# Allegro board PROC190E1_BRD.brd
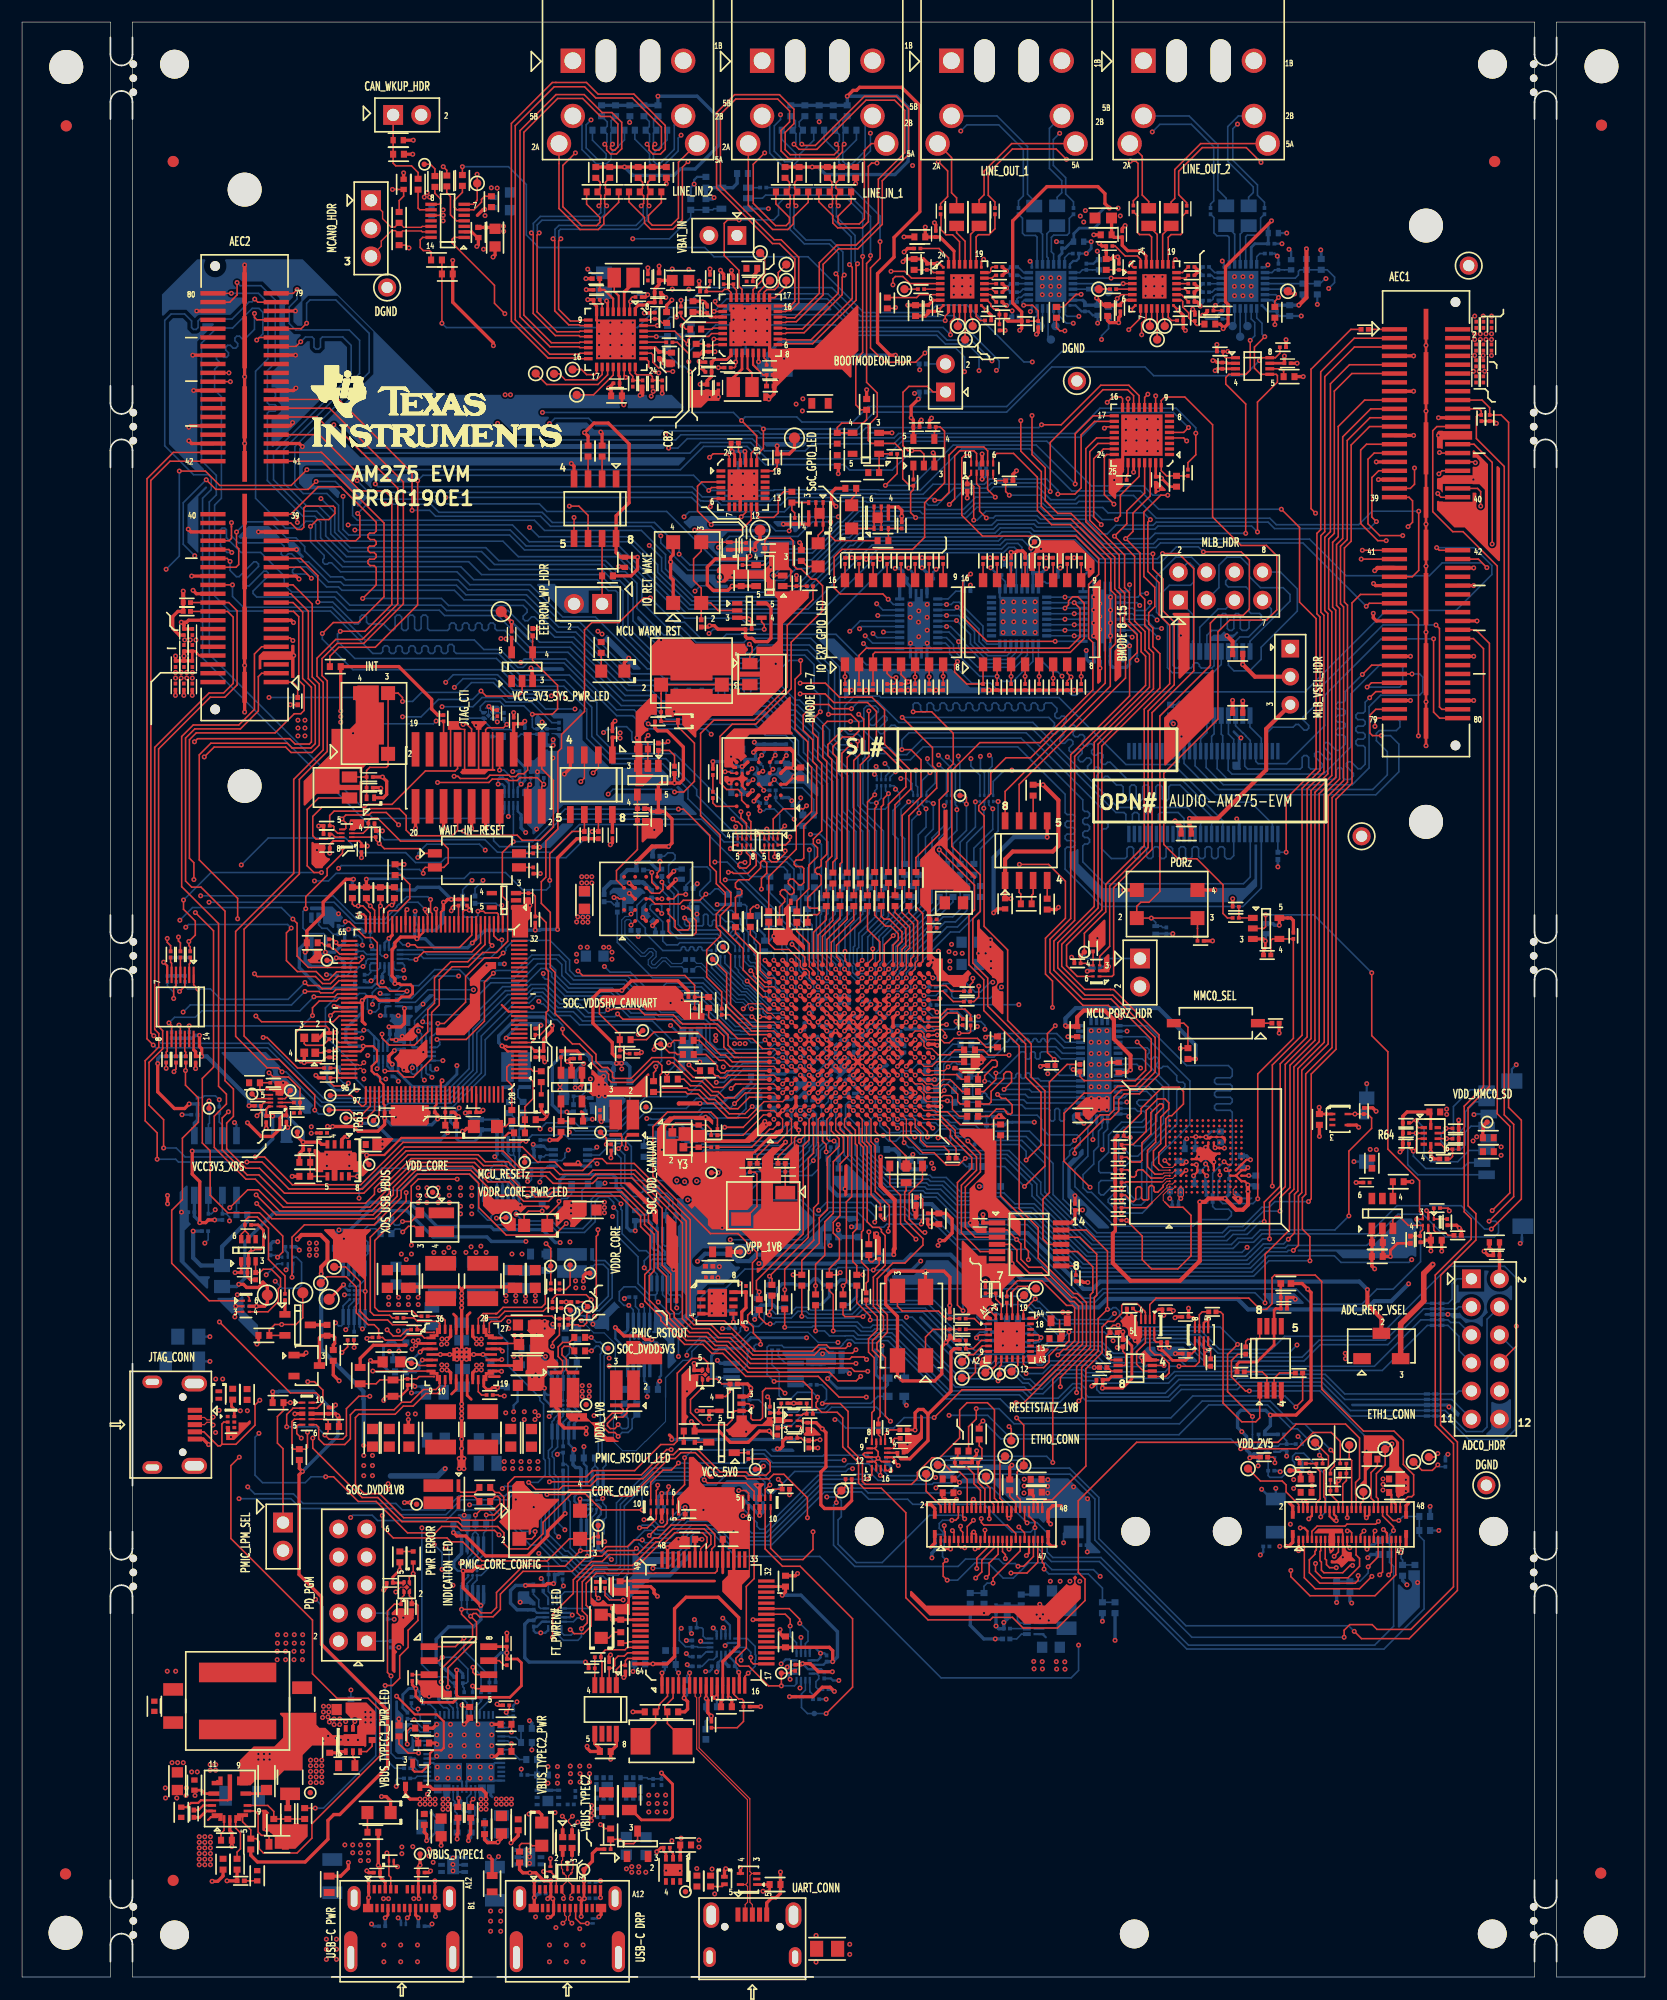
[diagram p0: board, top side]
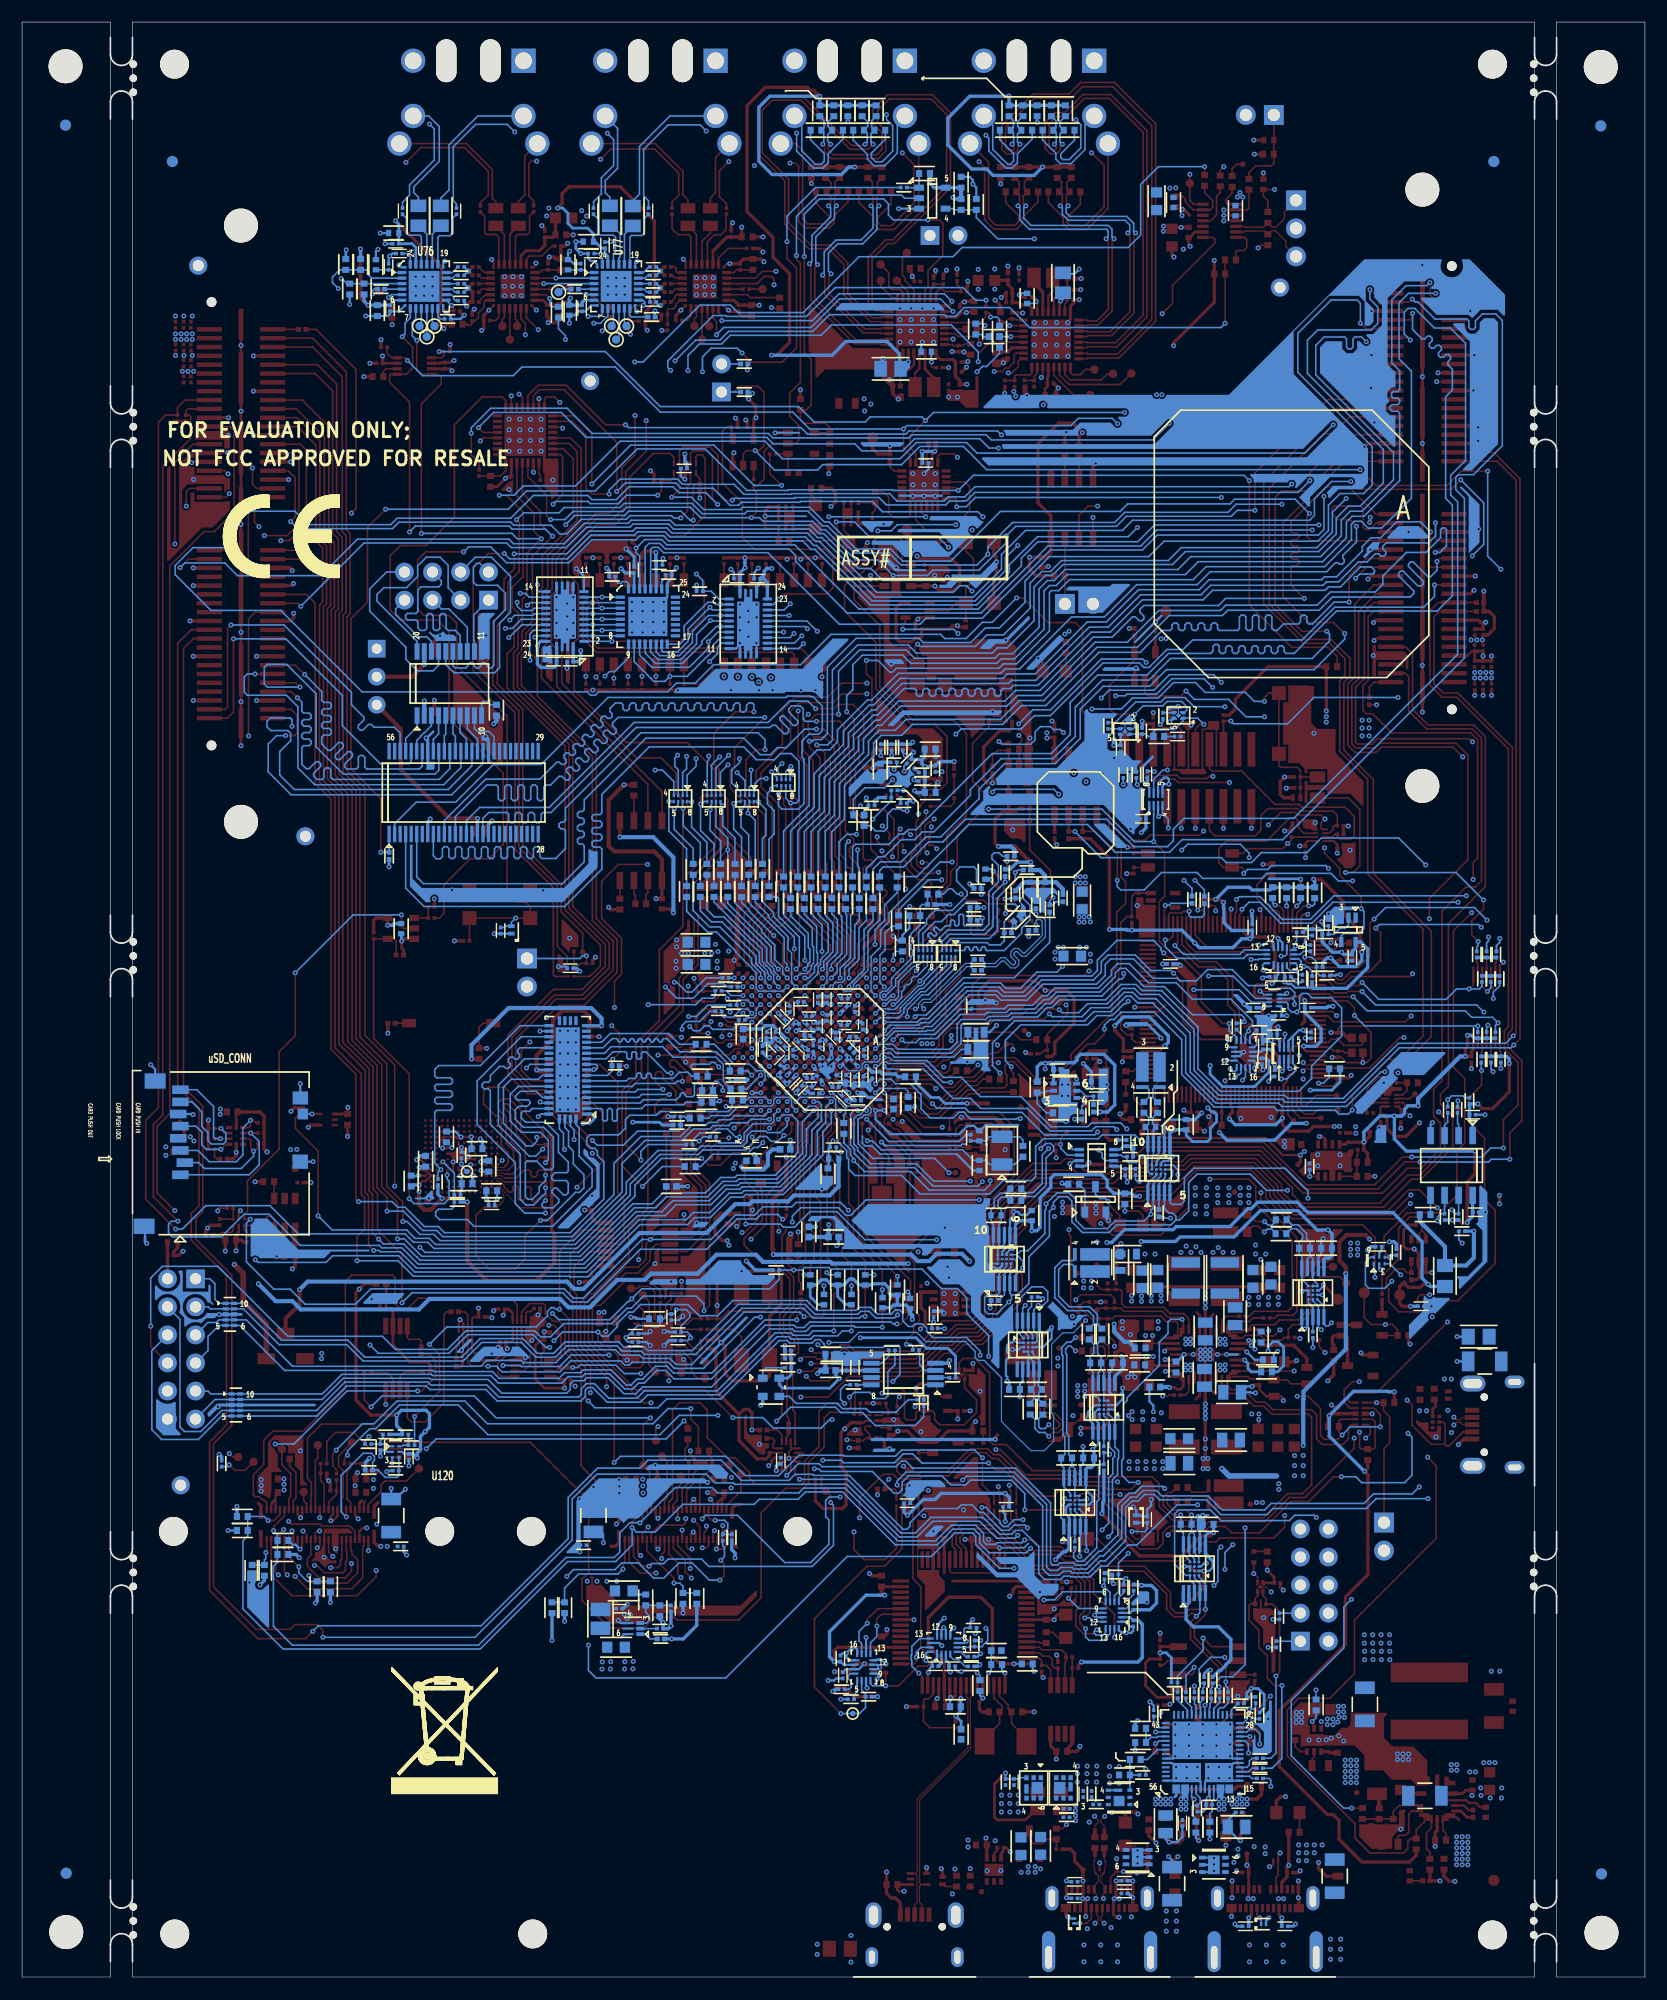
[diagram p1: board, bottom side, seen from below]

Outline 147 x 177 mm; copper layers: TOP, L02_GND1, L03_SIG1, L04_PWR1, L05_GND2, BOTTOM. Coordinates in mm from the lower left corner of the outline.
Outline path: 0,177 0,0 8,0 8,177 0,177 ; 10,177 10,0 137,0 137,177 10,177 ; 139,177 139,0 147,0 147,177 139,177

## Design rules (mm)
net group AEC1_GPIO0_1: nets AEC1_GPIO0_1 N28268314
net group AUDIO_EXT_REFCLK0: nets AUDIO_EXT_REFCLK0 N28087268
net group AUDIO_EXT_REFCLK1: nets AUDIO_EXT_REFCLK1 AUDIO_EXT_REFCLK1__R
net group AUDIO_EXT_REFCLK2: nets AUDIO_EXT_REFCLK2 AUDIO_EXT_REFCLK2_R
net group CAN_DP1: nets MCAN0_CAN_H MCAN0_CAN_L
net group CDCE_CLKOUT_1: nets CDCE_CLKOUT_1 N27176072
net group CPSW_RGMII1_TD0: nets CPSW_RGMII1_TD0 N28084397
net group CPSW_RGMII1_TD1: nets CPSW_RGMII1_TD1 N28084399
net group CPSW_RGMII1_TD2: nets CPSW_RGMII1_TD2 N28084409
net group CPSW_RGMII1_TD3: nets CPSW_RGMII1_TD3 N28084411
net group CPSW_RGMII1_TXC: nets CPSW_RGMII1_TXC CPSW_RGMII_TXC_R
net group CPSW_RGMII2_TD0: nets CPSW_RGMII2_TD0 N28084427
net group CPSW_RGMII2_TD2: nets CPSW_RGMII2_TD2 N28084431
net group CPSW_RGMII2_TD3: nets CPSW_RGMII2_TD3 N28084433
net group CPSW_RGMII2_TXC: nets CPSW_RGMII2_TXC CPSW_RGMII2_TXC_R
net group DP1_USB_SOC: nets SOC_USB0_DM SOC_USB0_DP
net group DP_CONN2: nets USBC_CONN2_DM USBC_CONN2_DP
net group DP_XDS_USB: nets XDS_USB_DM XDS_USB_DP
net group DVDD3V3: nets DVDD3V3_N DVDD3V3_P
net group HYPERBUS0_CK: nets HYPERBUS0_CK N28088261
net group HYPERBUS0_CK#: nets HYPERBUS0_CK# N28088302
net group HYPERBUS0_CS#: nets HYPERBUS0_CS# N28088339
net group HYPERBUS0_DQ0: nets HYPERBUS0_DQ0 SOC_HYPERBUS0_DQ0
net group HYPERBUS0_DQ1: nets HYPERBUS0_DQ1 SOC_HYPERBUS0_DQ1
net group HYPERBUS0_DQ2: nets HYPERBUS0_DQ2 SOC_HYPERBUS0_DQ2
net group HYPERBUS0_DQ3: nets HYPERBUS0_DQ3 SOC_HYPERBUS0_DQ3
net group HYPERBUS0_DQ4: nets HYPERBUS0_DQ4 SOC_HYPERBUS0_DQ4
net group HYPERBUS0_DQ5: nets HYPERBUS0_DQ5 SOC_HYPERBUS0_DQ5
net group HYPERBUS0_DQ6: nets HYPERBUS0_DQ6 SOC_HYPERBUS0_DQ6
net group HYPERBUS0_DQ7: nets HYPERBUS0_DQ7 SOC_HYPERBUS0_DQ7
net group HYPERBUS0_RWDS: nets HYPERBUS0_RWDS N27995683
net group MCASP0_ACLKR: nets MCASP0_ACLKR MCASP0_ACLKR_R
net group MCASP0_ACLKX: nets MCASP0_ACLKX N28061850
net group MCASP0_AFSR: nets MCASP0_AFSR MCASP0_AFSR_R
net group MCASP0_AFSX: nets MCASP0_AFSX MCASP0_AFSX_R
net group MCASP0_AXR0: nets MCASP0_AXR0 MCASP0_AXR0_R
net group MCASP0_AXR1: nets MCASP0_AXR1 MCASP0_AXR1_R
net group MCASP0_AXR2: nets MCASP0_AXR2 MCASP0_AXR2_R
net group MCASP0_AXR3: nets MCASP0_AXR3 MCASP0_AXR3_R
net group MCASP0_AXR4: nets MCASP0_AXR4 MCASP0_AXR4_R
net group MCASP0_AXR5: nets MCASP0_AXR5 MCASP0_AXR5_R
net group MCASP0_AXR6_R: nets MCASP0_AXR6_R UART2_RXD_FET
net group MCASP0_AXR7: nets MCASP0_AXR7 MCASP0_AXR7_R
net group MCASP0_AXR8_R: nets MCASP0_AXR8_R OBSCLK0
net group MCASP0_AXR9: nets MCASP0_AXR9 MCASP0_AXR9_R
net group MCASP1_ACLKR_R: nets MCASP1_ACLKR_R PCM6240_MCASP1_ACLKR
net group MCASP1_ACLKX_R: nets MCASP1_ACLKX_R TAD5212_MCASP1_ACLKX
net group MCASP1_AFSR_R: nets MCASP1_AFSR_R PCM6240_MCASP1_AFSR
net group MCASP1_AFSX_R: nets MCASP1_AFSX_R TAD5212_MCASP1_AFSX
net group MCASP1_AXR0_R: nets MCASP1_AXR0_R PCM6240_MCASP1_AXR0
net group MCASP1_AXR2_R: nets MCASP1_AXR2_R PCM6240_MCASP1_AXR2
net group MCASP2_ACLKR: nets MCASP2_ACLKR MCASP2_ACLKR_R
net group MCASP2_ACLKX: nets MCASP2_ACLKX MCASP2_ACLKX_R
net group MCASP2_AFSR: nets MCASP2_AFSR MCASP2_AFSR_R
net group MCASP2_AFSX: nets MCASP2_AFSX MCASP2_AFSX_R
net group MCASP2_AXR0: nets MCASP2_AXR0 MCASP2_AXR0_R
net group MCASP2_AXR1: nets MCASP2_AXR1 MCASP2_AXR1_R
net group MCASP2_AXR2: nets MCASP2_AXR2 MCASP2_AXR2_R
net group MCASP2_AXR3: nets MCASP2_AXR3 MCASP2_AXR3_R
net group MCASP2_AXR4: nets MCASP2_AXR4 MCASP2_AXR4_R
net group MCASP2_AXR5: nets MCASP2_AXR5 MCASP2_AXR5_R
net group MCASP3_ACLKX: nets MCASP3_ACLKX N28066500
net group MCASP3_AFSX: nets MCASP3_AFSX N28066472
net group MCASP3_AXR0: nets MCASP3_AXR0 N28066355
net group MCASP3_AXR1: nets MCASP3_AXR1 N28066391
net group MCASP3_AXR2: nets MCASP3_AXR2 N28066418
net group MCASP3_AXR3: nets MCASP3_AXR3 N28066445
net group MCASP4_ACLKR_R: nets MCASP4_ACLKR_FET MCASP4_ACLKR_R
net group MCASP4_AFSR_R: nets MCASP4_AFSR_FET MCASP4_AFSR_R
net group MCASP4_AXR0_R: nets MCASP4_AXR0_FET MCASP4_AXR0_R
net group MCASP4_AXR3_R: nets MCASP4_AXR3_FET MCASP4_AXR3_R
net group MCASP4_AXR4_R: nets MCASP4_AXR4_FET MCASP4_AXR4_R
net group MCASP4_AXR5_R: nets MCASP4_AXR5_FET MCASP4_AXR5_R
net group OSC1_XI: nets N27975321 OSC1_XI
net group OSC1_XO: nets N27975317 OSC1_XO
net group OSPI_CLK: nets OSPI_CLK SOC_OSPI_CLK
net group OSPI_DQS: nets OSPI_DQS OSPI_DQS_SOC
net group PCMPCM1_IN1: nets PCM1_IN1N PCM1_IN1P
net group PCMPCM1_IN2: nets PCM1_IN2N PCM1_IN2P
net group PCMPCM1_IN3: nets PCM1_IN3N PCM1_IN3P
net group PCMPCM1_IN4: nets PCM1_IN4N PCM1_IN4P
net group PCMPCM2_IN1: nets PCM2_IN1N PCM2_IN1P
net group PCMPCM2_IN2: nets PCM2_IN2N PCM2_IN2P
net group PCMPCM2_IN3: nets PCM2_IN3N PCM2_IN3P
net group PCMPCM2_IN4: nets PCM2_IN4N PCM2_IN4P
net group RESET_STATZ: nets RESET_STATZ RESETSTATZ_1V8
net group SEC_REF_N: nets N27175817 SEC_REF_N
net group SEC_REF_P: nets N27175821 SEC_REF_P
net group SOC_DVDD1V8: nets SOC_DVDD1V8_N SOC_DVDD1V8_P
net group SOC_DVDD3V3: nets SOC_DVDD3V3_N SOC_DVDD3V3_P
net group SOC_MMC0_CLK: nets MMC0_CLK SOC_MMC0_CLK
net group SOC_MMC0_CMD_R: nets SOC_MMC0_CMD SOC_MMC0_CMD_R
net group SOC_MMC0_DAT0_R: nets SOC_MMC0_DAT0 SOC_MMC0_DAT0_R
net group SOC_MMC0_DAT1_R: nets SOC_MMC0_DAT1 SOC_MMC0_DAT1_R
net group SOC_MMC0_DAT2_R: nets SOC_MMC0_DAT2 SOC_MMC0_DAT2_R
net group SOC_MMC0_DAT3_R: nets SOC_MMC0_DAT3 SOC_MMC0_DAT3_R
net group SOC_MMC0_DAT4_R: nets SOC_MMC0_DAT4 SOC_MMC0_DAT4_R
net group SOC_MMC0_DAT5_R: nets SOC_MMC0_DAT5 SOC_MMC0_DAT5_R
net group SOC_MMC0_DAT6_R: nets SOC_MMC0_DAT6 SOC_MMC0_DAT6_R
net group SOC_MMC0_DAT7_R: nets SOC_MMC0_DAT7 SOC_MMC0_DAT7_R
net group SOC_OSPI_DQ0: nets OSPI_DQ0 SOC_OSPI_DQ0
net group SOC_OSPI_DQ1: nets OSPI_DQ1 SOC_OSPI_DQ1
net group SOC_OSPI_DQ2: nets OSPI_DQ2 SOC_OSPI_DQ2
net group SOC_OSPI_DQ3: nets OSPI_DQ3 SOC_OSPI_DQ3
net group SOC_OSPI_DQ4: nets OSPI_DQ4 SOC_OSPI_DQ4
net group SOC_OSPI_DQ5: nets OSPI_DQ5 SOC_OSPI_DQ5
net group SOC_OSPI_DQ6: nets OSPI_DQ6 SOC_OSPI_DQ6
net group SOC_OSPI_DQ7: nets OSPI_DQ7 SOC_OSPI_DQ7
net group SOC_VDD_CANUART: nets SOC_VDD_CANUART_N SOC_VDD_CANUART_P
net group SOC_VDDSHV_CANUART: nets SOC_VDDSHV_CANUART_N SOC_VDDSHV_CANUART_P
net group VDD_0V85: nets VDD_0V85_N VDD_0V85_P
net group VDD_1V8: nets VDD_1V8_N VDD_1V8_P
net group VDD_CANUART: nets VDD_CANUART_N VDD_CANUART_P
net group VDD_CORE: nets VDD_CORE_N VDD_CORE_P
net group VDDA_1V8: nets VDDA_1V8_N VDDA_1V8_P
net group VDDR_CORE: nets VDDR_CORE_N VDDR_CORE_P
net group VDDSHV_CANUART: nets VDDSHV_CANUART_N VDDSHV_CANUART_P
net group WKUP_LFOSCO_XO: nets N27972730 WKUP_LFOSCO_XO
net group CPSW_RGMII2_TD1: nets N28084429
net group EMMC_MG: nets EMMC_CLK EMMC_CMD EMMC_D0 EMMC_D1 EMMC_D2 EMMC_D3 EMMC_D4 EMMC_D5 EMMC_D6 EMMC_D7
net group MCASP1_AXR1_R: nets MCASP1_AXR1_R TAD5212_1_DIN TAD5212_2_DIN TAD5212_3_DIN TAD5212_4_DIN TAD5212_MCASP1_AXR1
net group MCASP3_ACLKR: nets MCASP3_ACLKR MCASP4_ACLKX_FET MCASP4_ACLKX_R
net group MCASP3_AFSR: nets MCASP3_AFSR MCASP4_AFSX_FET MCASP4_AFSX_R
net group OSPI0_CSN0: nets N29295413 N29295438 OSPI0_CSN0 OSPI_CS
net group PWR: nets N24307354 N24307356 VCC1V8_SYS_N VCC_CORE_N VDDA_1V8_FB3 VDDA_ADC0
net group RGMII1_RD: nets CPSW_RGMII1_RD0 CPSW_RGMII1_RD1 CPSW_RGMII1_RD2 CPSW_RGMII1_RD3 CPSW_RGMII1_RX_DV CPSW_RGMII1_RXC
net group RGMII2_RD: nets CPSW_RGMII2_RD0 CPSW_RGMII2_RD1 CPSW_RGMII2_RD2 CPSW_RGMII2_RD3 CPSW_RGMII2_RX_DV CPSW_RGMII2_RXC
net group RGMII2_TD: nets CPSW_RGMII2_TX_EN
net group RGMII_TD: nets CPSW_RGMII1_TX_EN

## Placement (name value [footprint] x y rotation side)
C1  0.022uF  [CAP0402_0-75]  34.07 166.31 0 top
C2  0.1uF  [CAP0402_0-75]  58.36 163.39 270 top
C3  0.1uF  [CAP0402_0-75]  75.51 163.39 270 top
C11  22uF  [CAP0402_1]  51.63 161.63 0 top
C12  22uF  [CAP0402_1]  53.55 161.63 180 top
C13  22uF  [CAP0402_1]  55.47 161.63 0 top
C14  22uF  [CAP0402_1]  57.42 161.63 180 top
C15  22uF  [CAP0402_1]  68.77 161.63 0 top
C16  22uF  [CAP0402_1]  70.72 161.63 180 top
C17  22uF  [CAP0402_1]  72.66 161.63 0 top
C18  22uF  [CAP0402_1]  74.61 161.63 180 top
C20  1uF  [CAP0201_0-5]  100.66 160.11 270 top
C21  1uF  [CAP0201_0-5]  105.49 160.1 270 top
C22  1uF  [CAP0201_0-5]  83.2 159.88 270 top
C23  1uF  [CAP0201_0-5]  88.13 159.88 270 top
C24  47uF  [CAP0805_1-5]  84.65 159.34 270 top
C25  47uF  [CAP0805_1-5]  86.68 159.34 270 top
C26  47uF  [CAP0805_1-5]  102.05 159.34 270 top
C27  47uF  [CAP0805_1-5]  104.08 159.34 270 top
C28  0.1uF  [CAP0402_0-75]  122.76 65.24 0 top
C29  0.1uF  [CAP0201_0-5]  82.76 157.82 90 top
C30  0.1uF  [CAP0201_0-5]  99.65 157.79 90 top
C31  10uF  [CAP0402_0-75]  98.2 157.74 180 top
C32  10uF  [CAP0402_0-75]  81.32 157.55 180 top
C33  4.7uF  [CAP0402_0-75]  122.77 66.5 180 top
C35  1uF  [CAP0201_0-5]  98.48 156.72 180 top
C37  0.1uF  [CAP0402_0-75]  128.1 66.71 0 top
C38  1uF  [CAP0201_0-5]  81.09 156.5 180 top
C42  10uF  [CAP0402_0-75]  80.8 155.06 90 top
C43  10uF  [CAP0402_0-75]  98.2 155.06 90 top
C45  0.1uF  [CAP0201_0-5]  81.95 154.85 90 top
C46  0.1uF  [CAP0201_0-5]  99.35 154.85 90 top
C47  0.1uF  [CAP0201_0-5]  88.52 154.83 0 top
C48  0.1uF  [CAP0201_0-5]  105.92 154.83 0 top
C49  0.1uF  [CAP0402_0-75]  66.1 154.7 0 top
C50  0.1uF  [CAP0201_0-5]  88.52 154.07 0 top
C51  0.1uF  [CAP0201_0-5]  105.92 154.07 0 top
C52  2.2uF  [CAP0201_0-75]  57.7 153.95 90 top
C53  0.1uF  [CAP0201_0-5]  56.69 153.89 270 top
C54  2.2uF  [CAP0201_0-75]  51.98 153.77 180 top
C55  1uF  [CAP0201_0-5]  65.91 153.52 0 top
C56  0.1uF  [CAP0201_0-5]  88.52 153.31 0 top
C57  0.1uF  [CAP0201_0-5]  105.92 153.31 0 top
C60  0.1uF  [CAP0201_0-5]  52.04 152.76 0 top
C61  0.1uF  [CAP0201_0-5]  88.52 152.55 0 top
C62  0.1uF  [CAP0201_0-5]  105.92 152.55 0 top
C63  1uF  [CAP0201_0-5]  57.58 152.5 0 top
C64  0.1uF  [CAP0201_0-5]  55.85 152.11 0 top
C65  1uF  [CAP0201_0-5]  52.04 151.87 180 top
C66  1uF  [CAP0201_0-5]  88.52 151.66 0 top
C67  1uF  [CAP0201_0-5]  105.92 151.66 0 top
C68  0.1uF  [CAP0201_0-5]  57.58 151.61 0 top
C69  1uF  [CAP0201_0-5]  121.78 71.93 180 top
C70  220pF  [CAP0402_0-75]  124.66 72 0 top
C71  10uF  [CAP0402_0-75]  60.77 151.24 90 top
C72  0.1uF  [CAP0201_0-5]  82.08 151.09 270 top
C73  0.1uF  [CAP0201_0-5]  99.48 151.09 270 top
C74  0.1uF  [CAP0201_0-5]  62.07 150.95 90 top
C75  10uF  [CAP0402_0-75]  80.93 150.88 270 top
C76  10uF  [CAP0402_0-75]  98.33 150.88 270 top
C77  10uF  [CAP0402_0-75]  58.38 150.25 90 top
C78  0.1uF  [CAP0201_0-5]  57.33 150.42 90 top
C81  0.1uF  [CAP0201_0-5]  62.18 147.44 270 top
C82  10uF  [CAP0402_0-75]  61.06 147.38 270 top
C84  0.1uF  [CAP0201_0-5]  57.69 146.86 270 top
C85  10uF  [CAP0402_0-75]  58.83 146.58 270 top
C86  0.1uF  [CAP0201_0-5]  62.18 146.21 180 top
C87  1uF  [CAP0201_0-5]  67.71 145.95 0 top
C88  2.2uF  [CAP0402_0-75]  132.82 74.73 180 top
C89  0.1uF  [CAP0201_0-5]  63.91 145.71 180 top
C90  1uF  [CAP0201_0-5]  62.18 145.32 180 top
C92  0.1uF  [CAP0201_0-5]  67.71 145.06 180 top
C93  0.1uF  [CAP0402_0-75]  132.81 75.99 180 top
C95  1uF  [CAP0201_0-5]  53.85 144.3 180 top
C96  2.2uF  [CAP0201_0-75]  67.77 144.05 0 top
C97  0.1uF  [CAP0201_0-5]  63.07 143.93 90 top
C98  2.2uF  [CAP0201_0-75]  62.05 143.87 270 top
C99  0.1uF  [CAP0201_0-5]  114.63 146.11 0 top
C100  0.1uF  [CAP0402_0-75]  53.85 143.16 180 top
C101  0.1uF  [CAP0201_0-5]  108.71 145.89 90 top
C102  0.1uF  [CAP0402_0-75]  117.51 77.64 90 top
C103  0.1uF  [CAP0402_0-75]  127.96 78.32 180 top
C104  12pF  [CAP0201_0-5]  84.03 58.36 90 top
C105  12pF  [CAP0201_0-5]  84.04 59.89 90 top
C107  4700pF  [CAP0402_0-75]  34.56 162.31 90 top
C109  0.1uF  [CAP0402_0-75]  73.84 137.3 270 top
C121  10uF  [CAP0402_0-75]  93.55 57.8 0 top
C122  0.01uF  [CAP0201_0-5]  65.16 137.08 0 bottom
C126  0.01uF  [CAP0201_0-5]  102.68 135.56 90 top
C128  0.1uF  [CAP0201_0-5]  131.71 149.59 90 top
C129  0.1uF  [CAP0201_0-5]  132.37 149.59 90 top
C130  1uF  [CAP0201_0-5]  133.11 149.59 90 top
C133  0.1uF  [CAP0201_0-5]  131.7 147.53 270 top
C134  1uF  [CAP0201_0-5]  132.36 147.53 270 top
C135  1uF  [CAP0201_0-5]  133.1 147.53 270 top
C136  0.1uF  [CAP0201_0-5]  81.02 140.33 0 top
C137  0.1uF  [CAP0201_0-5]  131.7 146.1 90 top
C138  1uF  [CAP0201_0-5]  132.36 146.1 90 top
C140  0.1uF  [CAP0201_0-5]  53.47 112.51 90 top
C141  0.1uF  [CAP0201_0-5]  131.7 144.65 270 top
C142  1uF  [CAP0201_0-5]  132.36 144.65 270 top
C146  0.1uF  [CAP0402_0-75]  112.66 94.92 270 bottom
C147  0.1uF  [CAP0201_0-5]  53.47 103.38 270 top
C148  0.1uF  [CAP0402_0-75]  65.14 126.42 90 top
C149  4.7uF  [CAP0402_0-75]  70.53 109.02 90 top
C150  0.1uF  [CAP0201_0-5]  103.57 60.45 180 top
C151  0.1uF  [CAP0201_0-5]  103.45 57.48 180 top
C160  1uF  [CAP0201_0-5]  14.66 121.77 90 top
C161  0.1uF  [CAP0201_0-5]  15.42 121.77 90 top
C164  0.1uF  [CAP0201_0-5]  86.77 68.28 180 top
C165  0.1uF  [CAP0201_0-5]  95.37 69.72 270 top
C167  1uF  [CAP0201_0-5]  14.66 120.32 270 top
C168  0.1uF  [CAP0201_0-5]  15.42 120.32 270 top
C169  0.1uF  [CAP0201_0-5]  44.53 113.75 90 top
C170  1uF  [CAP0201_0-5]  13.9 118.89 90 top
C171  1uF  [CAP0201_0-5]  14.66 118.89 90 top
C172  0.1uF  [CAP0201_0-5]  15.42 118.89 90 top
C174  1uF  [CAP0201_0-5]  13.89 116.83 270 top
C175  0.1uF  [CAP0201_0-5]  14.65 116.83 270 top
C176  0.1uF  [CAP0201_0-5]  15.42 116.83 270 top
C182  100pF  [CAP0201_0-5]  77.64 65.29 270 top
C188  100pF  [CAP0201_0-5]  87.65 77.9 180 bottom
C190  0.01uF  [CAP0201_0-5]  45.87 97.85 270 top
C192  0.1uF  [CAP0201_0-5]  15.72 83.08 270 top
C197  1uF  [CAP0201_0-5]  50.27 83.16 180 top
C201  10uF  [CAP0402_1]  45.76 55.42 0 bottom
C202  10uF  [CAP0402_1]  83.04 68.65 270 top
C203  0.1uF  [CAP0201_0-5]  27.8 93.68 270 top
C205  18pF  [CAP0402_0-75]  61.28 76.68 90 top
C207  1uF  [CAP0201_0-5]  52.34 78.21 270 top
C208  0.01uF  [CAP0201_0-5]  42.99 91.72 180 bottom
C209  18pF  [CAP0402_0-75]  61.28 74.67 90 top
C213  12pF  [CAP0402_0-75]  60.29 76.16 270 bottom
C215  0.1uF  [CAP0201_0-5]  46.48 85.59 270 top
C216  12pF  [CAP0402_0-75]  60.29 73.48 90 bottom
C217  12pF  [CAP0201_0-5]  27.81 85.2 270 top
C221  0.01uF  [CAP0201_0-5]  46.48 83.56 270 top
C222  1uF  [CAP0201_0-5]  47.24 83.56 270 top
C223  12pF  [CAP0201_0-5]  27.81 83.54 90 top
C224  1uF  [CAP0201_0-5]  71.57 81.23 270 bottom
C225  0.1uF  [CAP0201_0-5]  27.65 81.41 0 top
C226  22uF  [CAP0603_1]  33.08 63.2 270 top
C227  47uF  [CAP0805_1-5]  34.99 63.2 270 top
C228  47uF  [CAP0805_1-5]  44.65 63.2 270 top
C229  22uF  [CAP0603_1]  46.48 63.2 270 top
C231  0.1uF  [CAP0201_0-5]  33.12 78.29 180 top
C232  0.01uF  [CAP0201_0-5]  37.11 78.29 180 top
C233  1uF  [CAP0201_0-5]  38.61 78.29 0 top
C234  0.01uF  [CAP0201_0-5]  40.85 78.29 180 top
C235  0.1uF  [CAP0201_0-5]  22.12 77.67 90 top
C236  0.1uF  [CAP0201_0-5]  23.94 77.72 90 top
C240  2.2uF  [CAP0402_0-75]  38.82 77.12 0 top
C241  1uF  [CAP0201_0-5]  27.34 76.42 180 top
C242  2.2uF  [CAP0603_1]  45.72 59.03 0 top
C243  15pF  [CAP0201_0-5]  25.74 74.9 0 top
C244  2.2uF  [CAP0402_0-75]  31.62 75.38 0 top
C245  100pF  [CAP0201_0-5]  60.92 87.42 270 top
C246  2.2uF  [CAP0603_1]  45.72 55.37 0 top
C247  2.2uF  [CAP0201_0-75]  62.24 64.34 180 top
C248  100pF  [CAP0201_0-5]  55.31 83.6 0 top
C249  2.2uF  [CAP0603_1]  33.46 55.69 180 top
C250  4.7uF  [CAP0402_0-75]  19.08 52.76 90 top
C251  0.1uF  [CAP0201_0-5]  62.22 63.35 180 top
C254  2.2uF  [CAP0603_1]  45.72 53.57 0 top
C255  1uF  [CAP0201_0-5]  65.57 62.28 90 top
C256  2.2uF  [CAP0603_1]  33.26 48.82 90 top
C257  22uF  [CAP0603_1]  35.04 48.82 90 top
C258  22uF  [CAP0603_1]  44.27 48.82 90 top
C259  2.2uF  [CAP0603_1]  42.18 48.74 180 bottom
C260  0.1uF  [CAP0603_1]  46.14 48.81 90 top
C261  0.1uF  [CAP0603_1]  31.75 48.82 90 top
C262  0.1uF  [CAP0402_0-75]  52.83 20.42 0 top
C263  4.7uF  [CAP0402_0-75]  54.17 35.34 270 top
C264  0.1uF  [CAP0402_0-75]  54.23 32.84 270 top
C265  1uF  [CAP0201_0-5]  77.63 56.74 0 bottom
C266  0.1uF  [CAP0201_0-5]  77.63 55.98 180 bottom
C267  0.1uF  [CAP0402_0-75]  20.39 52.74 90 top
C269  18pF  [CAP0402_0-75]  56.89 24 180 top
C270  18pF  [CAP0402_0-75]  58.94 24 0 top
C271  10uF  [CAP0402_0-75]  124.31 45.09 0 top
C272  10uF  [CAP0402_0-75]  83.88 45.09 0 top
C273  10uF  [CAP0402_0-75]  116.31 45.09 0 top
C274  10uF  [CAP0402_0-75]  91.86 45.06 0 top
C275  0.1uF  [CAP0402_0-75]  60.48 39.63 0 top
C276  0.1uF  [CAP0402_0-75]  116.31 43.88 0 top
C277  0.1uF  [CAP0402_0-75]  124.32 43.87 0 top
C278  0.1uF  [CAP0402_0-75]  83.88 43.84 0 top
C279  0.1uF  [CAP0402_0-75]  91.88 43.9 0 top
C280  0.1uF  [CAP0402_0-75]  63.8 24.47 180 top
C281  0.1uF  [CAP0402_0-75]  63.96 39.63 180 top
C282  0.1uF  [CAP0201_0-5]  65.63 24.48 180 top
C283  0.01uF  [CAP0201_0-5]  58.4 11.71 0 top
C284  0.1uF  [CAP0201_0-5]  71.57 55.2 270 bottom
C285  2.2uF  [CAP0402_0-75]  60.11 11.95 0 top
C286  1uF  [CAP0201_0-5]  72.33 55.2 270 bottom
C287  10uF  [CAP0402_0-75]  61.12 8.69 270 top
C288  0.1uF  [CAP0402_0-75]  69.15 30.34 270 top
C289  0.1uF  [CAP0402_0-75]  69.15 35.84 270 top
C290  10uF  [CAP0402_0-75]  73.74 56.38 180 bottom
C291  0.1uF  [CAP0402_0-75]  62.37 8.69 270 top
C292  0.1uF  [CAP0201_0-5]  43.91 30.19 90 top
C293  0.1uF  [CAP0201_0-5]  71.12 49.91 270 top
C295  0.1uF  [CAP0402_0-75]  68.21 8.37 0 top
C300  0.01uF  [CAP0201_0-5]  33.3 35.68 0 top
C301  0.01uF  [CAP0201_0-5]  43.85 24.6 180 top
C302  10uF  [CAP0603_1]  29.29 24.21 0 top
C303  4.7uF  [CAP0402_0-75]  40.54 23.95 270 top
C305  220pF  [CAP0402_0-75]  43.84 22.88 180 top
C306  220pF  [CAP0402_0-75]  36.1 22.53 0 top
C307  220pF  [CAP0402_0-75]  34.14 22.28 90 top
C308  330pF  [CAP0402_0-75]  31.71 21.94 90 top
C309  4.7uF  [CAP0402_0-75]  36.37 21.18 0 top
C310  1uF  [CAP0402_0-75]  27.86 20.79 90 top
C312  220pF  [CAP0402_0-75]  43.84 20.42 180 top
C317  47uF  [CAP0805_1-5]  52.93 15.92 270 top
C318  47uF  [CAP0805_1-5]  55.01 15.91 270 top
C319  10uF  [CAP0402_0-75]  39.48 14.9 90 top
C320  10uF  [CAP0402_0-75]  40.63 14.9 90 top
C321  0.1uF  [CAP0402_0-75]  36.43 14.26 270 top
C322  10uF  [CAP0603_1]  43.42 13.78 270 top
C323  0.1uF  [CAP0402_0-75]  44.94 13.78 270 top
C324  10uF  [CAP0603_1]  37.96 13.54 270 top
C325  0.1uF  [CAP0402_0-75]  41.89 13.43 270 top
C326  0.01uF  [CAP0201_0-5]  36.17 9.46 0 top
C327  0.01uF  [CAP0201_0-5]  32.14 9.45 180 top
C329  0.1uF  [CAP0402_0-75]  72.2 168.97 270 bottom
C330  0.1uF  [CAP0402_0-75]  55.06 168.97 270 bottom
C331  22uF  [CAP0402_1]  75.09 167.21 180 bottom
C332  22uF  [CAP0402_1]  73.14 167.21 0 bottom
C333  22uF  [CAP0402_1]  71.22 167.21 180 bottom
C334  22uF  [CAP0402_1]  69.3 167.21 0 bottom
C335  22uF  [CAP0402_1]  57.94 167.21 180 bottom
C336  22uF  [CAP0402_1]  56 167.21 0 bottom
C337  22uF  [CAP0402_1]  54.08 167.21 180 bottom
C338  22uF  [CAP0402_1]  52.16 167.21 0 bottom
C340  0.1uF  [CAP0402_0-75]  61.94 162.5 90 bottom
C341  1uF  [CAP0201_0-5]  112.54 159.88 270 bottom
C342  1uF  [CAP0201_0-5]  107.65 159.88 270 bottom
C343  1uF  [CAP0201_0-5]  95.24 159.88 270 bottom
C344  1uF  [CAP0201_0-5]  90.26 159.88 270 bottom
C345  47uF  [CAP0805_1-5#2]  111.1 159.47 270 bottom
C346  47uF  [CAP0805_1-5#2]  109.07 159.47 270 bottom
C347  47uF  [CAP0805_1-5#2]  93.76 159.47 270 bottom
C348  47uF  [CAP0805_1-5#2]  91.68 159.44 270 bottom
C349  10uF  [CAP0402_0-75]  113.34 157.9 0 bottom
C350  10uF  [CAP0402_0-75]  95.7 157.12 0 bottom
C351  0.1uF  [CAP0201_0-5]  113.16 156.93 0 bottom
C352  0.1uF  [CAP0201_0-5]  94.2 156.8 90 bottom
C353  1uF  [CAP0201_0-5]  112.85 156.04 0 bottom
C354  1uF  [CAP0201_0-5]  95.45 156.04 0 bottom
C355  10uF  [CAP0402_0-75]  114.95 155.03 90 bottom
C356  10uF  [CAP0402_0-75]  97.55 155.03 90 bottom
C357  0.1uF  [CAP0201_0-5]  113.8 154.85 90 bottom
C358  0.1uF  [CAP0201_0-5]  96.4 154.85 90 bottom
C359  0.1uF  [CAP0201_0-5]  107.24 154.83 180 bottom
C360  0.1uF  [CAP0201_0-5]  89.84 154.83 180 bottom
C361  0.1uF  [CAP0201_0-5]  107.24 154.07 180 bottom
C362  0.1uF  [CAP0201_0-5]  89.84 154.07 180 bottom
C363  1uF  [CAP0805_1-5#2]  52.71 153.4 90 bottom
C364  0.1uF  [CAP0201_0-5]  107.24 153.31 180 bottom
C365  0.1uF  [CAP0201_0-5]  89.84 153.31 180 bottom
C366  0.1uF  [CAP0201_0-5]  107.24 152.55 180 bottom
C367  0.1uF  [CAP0201_0-5]  89.84 152.55 180 bottom
C368  10uF  [CAP0402_0-75]  55.96 151.99 90 bottom
C369  1uF  [CAP0201_0-5]  107.24 151.78 180 bottom
C370  1uF  [CAP0201_0-5]  89.84 151.66 180 bottom
C371  0.1uF  [CAP0201_0-5]  113.67 151.09 270 bottom
C372  0.1uF  [CAP0201_0-5]  96.27 151.09 270 bottom
C373  10uF  [CAP0402_0-75]  114.82 150.88 270 bottom
C374  10uF  [CAP0402_0-75]  97.43 150.91 270 bottom
C378  10uF  [CAP0402_0-75]  65.09 147.15 0 bottom
C379  1uF  [CAP0805_1-5#2]  68.33 145.61 0 bottom
C382  0.1uF  [CAP0201_0-5]  87.58 58.39 0 bottom
C383  0.1uF  [CAP0201_0-5]  87.58 57.63 0 bottom
C384  0.1uF  [CAP0201_0-5]  88.21 59.75 270 bottom
C385  10uF  [CAP0402_0-75]  89.72 59.59 0 bottom
C386  0.1uF  [CAP0201_0-5]  91.46 58.25 180 bottom
C387  0.1uF  [CAP0201_0-5]  91.46 57.49 180 bottom
C388  0.1uF  [CAP0402_0-75]  64.75 111.17 180 bottom
C389  0.1uF  [CAP0402_0-75]  69.26 109.36 270 bottom
C390  0.1uF  [CAP0402_0-75]  64.74 107.24 180 bottom
C391  0.1uF  [CAP0201_0-5]  89.28 127.84 0 bottom
C393  0.1uF  [CAP0201_0-5]  91.56 127.41 270 bottom
C394  0.1uF  [CAP0201_0-5]  82.25 126.61 180 bottom
C395  0.1uF  [CAP0201_0-5]  80.41 126.61 0 bottom
C408  0.1uF  [CAP0201_0-5]  98.86 119.09 0 bottom
C409  0.1uF  [CAP0201_0-5]  97.36 119.09 180 bottom
C414  0.1uF  [CAP0201_0-5]  24.12 66.12 180 bottom
C415  0.01uF  [CAP0201_0-5]  43.05 114.43 270 top
C416  0.01uF  [CAP0201_0-5]  47.49 111.24 90 bottom
C417  8.2pF  [CAP0201_0-5]  42.33 112.31 180 bottom
C421  0.1uF  [CAP0201_0-5]  97.35 91.34 180 bottom
C427  0.1uF  [CAP0402_0-75]  57.11 53.21 180 bottom
C428  0.1uF  [CAP0402_0-75]  55.11 53.21 0 bottom
C429  1uF  [CAP0201_0-5]  76.53 80.5 315 bottom
C430  0.1uF  [CAP0201_0-5]  35.57 95.04 270 bottom
C432  1uF  [CAP0201_0-5]  72.5 88.58 180 bottom
C434  1uF  [CAP0201_0-5]  71.57 87.67 90 bottom
C437  1uF  [CAP0201_0-5]  73.31 80.57 180 bottom
C440  1uF  [CAP0201_0-5]  70.86 86.06 270 bottom
C441  0.1uF  [CAP0201_0-5]  73.32 82.87 315 bottom
C443  1uF  [CAP0201_0-5]  78.13 82.76 315 bottom
C445  0.1uF  [CAP0201_0-5]  78.11 81.23 225 bottom
C446  1uF  [CAP0201_0-5]  79.57 85.29 270 bottom
C447  0.1uF  [CAP0201_0-5]  72.53 86.17 180 bottom
C448  0.1uF  [CAP0201_0-5]  72.5 87.66 135 bottom
C449  22pF  [CAP0201_0-5]  72.49 82.82 315 bottom
C451  1uF  [CAP0201_0-5]  72.52 79.6 225 bottom
C453  1uF  [CAP0201_0-5]  74.1 88.49 90 bottom
C454  1uF  [CAP0201_0-5]  75.65 81.39 180 bottom
C455  0.1uF  [CAP0201_0-5]  26.5 92.3 90 bottom
C460  0.1uF  [CAP0201_0-5]  75.73 86.07 225 bottom
C461  1uF  [CAP0201_0-5]  74.92 88.47 90 bottom
C462  0.1uF  [CAP0201_0-5]  73.31 85.23 90 bottom
C463  1uF  [CAP0201_0-5]  76.62 86.03 90 bottom
C465  0.1uF  [CAP0201_0-5]  78.12 86.87 45 bottom
C466  0.1uF  [CAP0201_0-5]  74.75 84.46 90 bottom
C467  1uF  [CAP0201_0-5]  77.32 86.09 135 bottom
C468  0.1uF  [CAP0201_0-5]  74.9 86.12 270 bottom
C469  0.1uF  [CAP0201_0-5]  33.72 90.55 180 bottom
C470  0.1uF  [CAP0201_0-5]  32.35 90.55 0 bottom
C471  1uF  [CAP0201_0-5]  78.76 85.29 270 bottom
C473  0.1uF  [CAP0201_0-5]  15.33 69.25 0 bottom
C477  0.1uF  [CAP0201_0-5]  78.12 82.09 135 bottom
C478  0.1uF  [CAP0201_0-5]  46.94 75.5 270 bottom
C483  1uF  [CAP0201_0-5]  82.03 68.86 270 top
C484  1uF  [CAP0201_0-5]  70.77 83.68 90 bottom
C485  1uF  [CAP0201_0-5]  73.97 84.61 45 bottom
C488  1uF  [CAP0201_0-5]  30.54 87.76 180 bottom
C489  0.1uF  [CAP0201_0-5]  31.49 108.65 180 top
C490  0.1uF  [CAP0201_0-5]  76.46 88.32 180 bottom
C493  0.1uF  [CAP0201_0-5]  77.16 83.66 270 bottom
C494  0.1uF  [CAP0201_0-5]  75.72 86.98 0 bottom
C495  1uF  [CAP0201_0-5]  82.57 95.76 180 top
C497  4.7uF  [CAP0201_0-5]  82.57 95 180 top
C498  0.1uF  [CAP0402_0-75]  108.56 76.06 90 bottom
C500  0.1uF  [CAP0201_0-5]  35.47 87.76 180 bottom
C501  1uF  [CAP0201_0-5]  74.1 82.86 315 bottom
C502  1uF  [CAP0201_0-5]  71.84 83.88 45 bottom
C503  0.1uF  [CAP0402_0-75]  110.45 73.85 90 bottom
C504  2.2uF  [CAP0402_0-75]  105.79 75 0 bottom
C505  0.1uF  [CAP0201_0-5]  77.31 82.04 315 bottom
C506  1uF  [CAP0201_0-5]  75.65 80.41 315 bottom
C508  1uF  [CAP0201_0-5]  71.29 79.35 0 bottom
C509  1uF  [CAP0201_0-5]  70.79 81.26 270 bottom
C511  0.1uF  [CAP0201_0-5]  33.18 87.04 180 bottom
C512  1uF  [CAP0201_0-5]  71.7 82.84 45 bottom
C514  0.1uF  [CAP0402_0-75]  104.73 73.41 270 bottom
C515  0.1uF  [CAP0201_0-5]  33.59 85.35 180 bottom
C516  0.1uF  [CAP0201_0-5]  30.24 85.27 270 bottom
C517  1uF  [CAP0201_0-5]  72.38 80.46 90 bottom
C518  2.2uF  [CAP0402_0-75]  111.75 72.07 90 bottom
C520  0.1uF  [CAP0402_0-75]  106.69 71.83 0 bottom
C521  0.1uF  [CAP0402_0-75]  104.47 71.19 180 bottom
C524  0.1uF  [CAP0402_0-75]  30.83 65.98 180 bottom
C525  0.1uF  [CAP0402_0-75]  28.83 65.98 0 bottom
C527  1uF  [CAP0201_0-5]  104.46 69.86 180 bottom
C528  0.1uF  [CAP0201_0-5]  33.54 81.82 90 bottom
C529  0.1uF  [CAP0201_0-5]  15.61 78.07 0 bottom
C532  0.1uF  [CAP0603_1]  33.88 63.5 270 bottom
C533  100uF  [CAP1210_2-75]  41.58 63.29 270 bottom
C534  100uF  [CAP1210_2-75]  38.05 63.29 270 bottom
C535  2.2uF  [CAP0603_1]  44.12 63.21 270 bottom
C536  2.2uF  [CAP0603_1]  35.51 63.21 270 bottom
C537  0.1uF  [CAP0603_1]  45.53 63.16 270 bottom
C538  0.1uF  [CAP0201_0-5]  20.29 60.73 180 bottom
C546  10uF  [CAP0805_1-5]  37.12 59.82 90 bottom
C547  10uF  [CAP0805_1-5]  39.82 58.45 270 bottom
C555  0.47uF  [CAP0402_0-75]  44.4 53.42 0 bottom
C559  0.1uF  [CAP0402_0-75]  49.76 55.6 180 bottom
C560  0.1uF  [CAP0402_0-75]  47.76 55.6 0 bottom
C561  4.7uF  [CAP0402_0-75]  42.47 55.23 90 bottom
C565  10uF  [CAP0805_1-5]  39.9 54.25 90 bottom
C572  10uF  [CAP0805_1-5]  37.39 52.94 180 bottom
C574  0.1uF  [CAP0201_0-5]  46.35 33.53 270 bottom
C575  0.1uF  [CAP0201_0-5]  46.35 32 90 bottom
C576  0.47uF  [CAP0402_0-75]  34.76 57.94 90 bottom
C592  47uF  [CAP0805_1-5]  42.17 46.51 180 bottom
C593  47uF  [CAP0805_1-5]  37.49 48.62 0 bottom
C597  0.1uF  [CAP0402_0-75]  52.39 46.99 180 bottom
C598  0.1uF  [CAP0402_0-75]  50.39 46.99 0 bottom
C599  0.1uF  [CAP0402_0-75]  55.95 28.35 0 bottom
C602  0.1uF  [CAP0201_0-5]  111.96 47.09 270 bottom
C603  0.1uF  [CAP0402_0-75]  41.56 40.98 180 bottom
C604  0.1uF  [CAP0402_0-75]  39.56 40.98 0 bottom
C605  1000pF  [CAP1206_1-75]  14.51 55.74 180 bottom
C606  0.1uF  [CAP0402_0-75]  58.72 28.29 0 bottom
C607  0.1uF  [CAP0402_0-75]  62.46 24.47 180 bottom
C608  0.1uF  [CAP0201_0-5]  62.76 28.14 0 bottom
C609  0.1uF  [CAP0201_0-5]  58.16 114.54 180 top
C610  1000pF  [CAP1206_1-75]  95.24 41.8 90 bottom
C611  1000pF  [CAP1206_1-75]  113.56 41.78 90 bottom
C612  0.1uF  [CAP0201_0-5]  64.28 28.14 180 bottom
C613  0.1uF  [CAP0201_0-5]  45.09 41.41 270 bottom
C614  22uF  [CAP0603_1]  92.49 34.96 180 bottom
C615  120pF  [CAP0201_0-5]  88.22 33.37 90 bottom
C616  0.1uF  [CAP0201_0-5]  92.91 33.35 180 bottom
C617  0.1uF  [CAP0201_0-5]  72.66 27.31 90 bottom
C618  0.1uF  [CAP0201_0-5]  72.87 28.83 270 bottom
C620  4.7uF  [CAP0603_1]  93.2 29.85 0 bottom
C622  0.1uF  [CAP0201_0-5]  103.65 94.74 90 bottom
C631  4.7uF  [CAP0402_0-75]  45.68 21.24 0 bottom
C638  0.1uF  [CAP0201_0-5]  57.16 17.65 90 bottom
C639  0.1uF  [CAP0201_0-5]  50.88 16.56 270 bottom
C640  0.1uF  [CAP0201_0-5]  52.38 15.23 180 bottom
C641  0.01uF  [CAP0201_0-5]  36.78 14.9 0 bottom
C642  0.01uF  [CAP0201_0-5]  41.9 13.93 270 bottom
C643  4.7uF  [CAP0805_1-5]  36.99 13.58 0 bottom
C644  4.7uF  [CAP0805_1-5]  43.42 13.83 270 bottom
C646  10uF  [CAP0603_1]  54.74 11.87 270 bottom
C647  10uF  [CAP0603_1]  56.52 11.84 270 bottom
C648  1000pF  [CAP1206_1-75]  28.1 9.13 90 bottom
C649  0.01uF  [CAP0201_0-5]  47.16 8.72 180 bottom
C650  0.01uF  [CAP0201_0-5]  51.67 8.61 0 bottom
C651  1000pF  [CAP1206_1-75]  42.83 8.45 90 bottom
C652  0.01uF  [CAP0201_0-5]  47.15 7.56 180 bottom
C653  0.01uF  [CAP0201_0-5]  51.66 7.12 0 bottom
C654  0.01uF  [CAP0201_0-5]  36.17 4.59 0 bottom
C655  0.01uF  [CAP0201_0-5]  32.61 4.59 180 bottom
C657  1uF  [CAP0201_0-5]  74.09 86.85 90 bottom
C658  1uF  [CAP0201_0-5]  75.34 84.05 90 bottom
C659  1uF  [CAP0201_0-5]  72.5 83.64 225 bottom
C660  1uF  [CAP0201_0-5]  74.91 82.18 180 bottom
C662  0.1uF  [CAP0201_0-5]  77.46 87.65 90 bottom
C663  0.1uF  [CAP0201_0-5]  75.88 85.24 180 bottom
C787  0.1uF  [CAP0402_0-75]  99.33 82.35 90 top
C3494  0.1uF  [CAP0402_0-75]  14.42 14.91 90 top
C3497  0.1uF  [CAP0402_0-75]  11.98 24.51 270 top
C3625  10uF  [CAP1206_2]  24.27 18.08 90 top
C3627  10uF  [CAP0402_1]  18.51 12.38 180 top
C3628  10uF  [CAP1206_2]  19.93 16.41 0 bottom
C3629  0.22uF  [CAP0603_1]  22.14 17.73 90 top
C3630  0.22uF  [CAP0603_1]  14.06 17.73 90 top
C3631  0.1uF  [CAP0402_0-75]  15.61 17.37 90 top
C3636  47uF  [CAP1206_2]  13.68 24.54 270 top
C3637  47uF  [CAP1206_2]  25.37 24.69 270 top
C3638  47uF  [CAP1206_2]  25.37 24.69 270 bottom
C3639  33pF  [CAP0402_0-75]  21.3 9.16 90 top
C3642  0.01uF  [CAP0201_0-5]  49.67 79.74 180 bottom
C3643  1uF  [CAP0402_0-75]  49.69 81.07 180 bottom
C3644  2.2uF  [CAP0201_0-75]  53.23 82.16 0 bottom
C3645  1uF  [CAP0201_0-5]  79.93 83.99 90 bottom
C3647  1uF  [CAP0201_0-5]  73.45 81.87 45 bottom
C3649  1uF  [CAP0201_0-5]  78.12 84.44 45 bottom
C3652  1uF  [CAP0201_0-5]  74.78 81.4 45 bottom
C3653  1uF  [CAP0201_0-5]  70 81.66 270 bottom
C3655  1uF  [CAP0201_0-5]  78.9 84.43 45 bottom
C3656  1uF  [CAP0201_0-5]  75.08 80 0 bottom
C3657  12pF  [CAP0201_0-5]  69.41 72.9 180 top
C3658  12pF  [CAP0201_0-5]  65.65 72.87 180 top
C3659  0.1uF  [CAP0402_0-75]  95.57 85.6 270 top
C3660  0.1uF  [CAP0402_0-75]  96.08 78 0 top
C3661  0.1uF  [CAP0201_0-5]  77.3 81.24 315 bottom
C3692  0.1uF  [CAP0402_0-75]  41.33 157.95 90 top
C3694  0.1uF  [CAP0402_0-75]  42.7 160.67 90 bottom
C3695  4.7uF  [CAP0603_1]  42.84 157.49 90 top
C3696  4.7uF  [CAP0603_1]  44.24 160.78 90 bottom
C3697  0.1uF  [CAP0402_0-75]  37.09 159.92 270 bottom
C3698  0.1uF  [CAP0402_0-75]  105.45 103.53 180 top
C3701  0.1uF  [CAP0402_0-75]  110.11 114.47 180 top
C3702  0.1uF  [CAP0402_0-75]  110.11 119.78 180 top
C3703  0.1uF  [CAP0201_0-5]  87.05 136.59 0 bottom
C3704  0.1uF  [CAP0201_0-5]  97.6 54.09 0 top
C3705  0.1uF  [CAP0402_0-75]  57.64 105.07 270 top
C3706  4.7uF  [CAP0402_0-75]  55.71 98.66 90 bottom
C3707  0.1uF  [CAP0402_0-75]  56.83 95.91 135 bottom
C3708  0.1uF  [CAP0402_0-75]  59.75 99.85 90 bottom
C3709  0.1uF  [CAP0402_0-75]  54.34 98.66 270 bottom
C3710  330pF  [CAP0402_0-75]  67.7 62.2 270 bottom
C3711  330pF  [CAP0402_0-75]  70.63 63.12 270 bottom
C3712  330pF  [CAP0402_0-75]  74.36 61.34 270 bottom
C3713  330pF  [CAP0402_0-75]  75.61 63.12 270 bottom
C3714  330pF  [CAP0402_0-75]  66.57 60.98 270 bottom
C3715  330pF  [CAP0402_0-75]  69.05 61.06 270 bottom
C3716  330pF  [CAP0402_0-75]  73.12 63.12 270 bottom
C3717  330pF  [CAP0402_0-75]  71.87 61.34 270 bottom
C3718  0.1uF  [CAP0201_0-5]  57.86 42.57 0 bottom
C3719  0.1uF  [CAP0201_0-5]  66.83 42.9 180 bottom
C3720  0.1uF  [CAP0201_0-5]  78.28 46.74 90 bottom
C3721  0.1uF  [CAP0201_0-5]  79.57 47.46 180 top
C3724  0.1uF  [CAP0201_0-5]  34.69 82.9 90 bottom
C3725  0.1uF  [CAP0201_0-5]  34.61 84.26 270 bottom
C3726  0.1uF  [CAP0201_0-5]  45.48 104.86 180 bottom
C3727  0.1uF  [CAP0201_0-5]  45.06 108.9 270 bottom
C3728  0.1uF  [CAP0201_0-5]  44.34 121.54 270 top
C3729  0.1uF  [CAP0201_0-5]  30.74 102.12 90 top
C3730  0.1uF  [CAP0201_0-5]  27.59 102.22 0 top
C3731  0.1uF  [CAP0201_0-5]  27.75 51.28 90 top
C3732  0.1uF  [CAP0402_0-75]  89.04 97.17 90 top
C3733  0.1uF  [CAP0402_0-75]  54.6 128.09 270 top
C3738  2.2uF  [CAP0603_1]  45.81 57.26 0 top
C3740  0.1uF  [CAP0201_0-5]  65.81 122.03 180 top
C3741  0.1uF  [CAP0201_0-5]  65.58 129.57 90 top
C3742  4.7uF  [CAP0402_0-75]  73.48 74.09 0 bottom
C3743  0.1uF  [CAP0201_0-5]  73.53 75.13 180 bottom
C3744  4.7uF  [CAP0402_0-75]  133.37 66.52 180 top
C3745  0.1uF  [CAP0201_0-5]  133.55 65.33 0 top
C3746  0.1uF  [CAP0201_0-5]  20.47 68.1 180 top
C3747  1uF  [CAP0201_0-5]  20.13 63.78 0 top
C3750  22pF  [CAP0201_0-5]  34.92 53.88 90 top
C3751  1uF  [CAP0201_0-5]  72.37 81.39 270 bottom
C3752  1uF  [CAP0201_0-5]  75.79 83.66 90 bottom
C3753  4.7uF  [CAP0603_1]  85.9 91.68 0 bottom
C3754  4.7uF  [CAP0603_1]  50.98 97.47 90 bottom
C3755  2.2uF  [CAP0603_1]  50.93 97.52 90 top
C3756  22uF  [CAP0603_1]  51.87 92.43 180 bottom
C3757  22uF  [CAP0603_1]  85.9 93.69 0 bottom
C3758  0.1uF  [CAP0201_0-5]  74.76 82.88 270 bottom
C3759  0.1uF  [CAP0201_0-5]  71.72 85.14 180 bottom
C3760  2.2uF  [CAP0603_1]  51.24 69.44 180 top
C3761  0.1uF  [CAP0402_0-75]  58.77 68.96 180 bottom
C3762  0.1uF  [CAP0402_0-75]  55.54 68.94 90 bottom
C3763  0.1uF  [CAP0402_0-75]  44.78 76.96 180 bottom
C3764  0.1uF  [CAP0402_0-75]  41.55 77.17 90 bottom
C3767  0.1uF  [CAP0201_0-5]  76.51 84.46 225 bottom
C3768  0.1uF  [CAP0201_0-5]  105.38 59.77 0 top
C3769  0.1uF  [CAP0201_0-5]  105.4 56.44 0 top
C3771  0.1uF  [CAP0201_0-5]  114.3 60.5 180 top
C3772  1uF  [CAP0201_0-5]  114.3 61.52 180 top
C3773  0.1uF  [CAP0201_0-5]  61.96 51.26 180 top
C3774  0.1uF  [CAP0201_0-5]  60.87 54.65 90 top
D1  TPD1E10B06DPYR  [DIO_DFN0402_0-5]  17.82 52.69 270 top
D2  PLVA650A  [DIO_SOT23_123]  25.78 55.36 0 top
D3  TPD1E10B06DPYR  [DIO_DFN0402_0-5]  63.62 8.73 270 top
D5  BAT54CWT1G  [DIO_SOT323-3_1-1]  35.38 18.31 90 top
D6  BZX84C6V8LT1G  [SOT23-123_1-2]  55.75 12.06 90 top
D7  TPD1E01B04DPLT  [DIO_DFN0201_0-4]  33.45 10.52 0 top
D8  TPD1E01B04DPLT  [DIO_DFN0201_0-4]  47.86 9.77 90 top
D9  ESD122DMXR  [X2SON3_ESD122DMX_30X40_0-4]  49.39 9.53 270 top
D11  TPD1E10B06DPYR  [DIO_DFN0402_0-5]  31.55 106.77 180 top
D12  TPD1E10B06DPYR  [DIO_DFN0402_0-5]  59.75 113.69 180 top
D13  TPD1E10B06DPYR  [DIO_DFN0402_0-5]  46.09 41.47 270 bottom
D14  TPD1E10B06DPYR  [DIO_DFN0402_0-5]  102.68 94.81 90 bottom
D16  TPD1E01B04DPLT  [DIO_DFN0201_0-4]  51.69 5.07 90 bottom
D17  TPD1E01B04DPLT  [DIO_DFN0201_0-4]  34.54 4.79 180 bottom
D18  TPD1E10B06DPYR  [DIO_DFN0402_0-5]  64.06 129.57 90 top
FL1  120E  [EMIFIL_BLM18P_0603_0-8]  97.93 159.26 0 top
FL2  120E  [EMIFIL_BLM18P_0603_0-8]  59.64 153.61 180 top
FL4  120E  [EMIFIL_BLM15A_0402_0-6]  122.27 73.68 90 top
FL6  120E  [EMIFIL_BLM15A_0402_0-6]  77.87 74.93 180 bottom
FL8  26E  [EMIFIL_BLM18K_0603]  84.41 97.26 180 top
FL9  120E  [EMIFIL_BLM15A_0402_0-6]  68.06 79.04 90 bottom
FL10  120E  [EMIFIL_BLM15A_0402_0-6]  73.77 54.92 0 bottom
FL13  120E  [EMIFIL_BLM15A_0402_0-6]  88.18 71.58 180 bottom
FL17  120E  [EMIFIL_BLM15A_0402_0-6]  58.75 29.56 180 bottom
FL18  120E  [EMIFIL_BLM15A_0402_0-6]  61.94 21.97 270 bottom
FL19  120E  [EMIFIL_BLM15A_0402_0-6]  81.68 85.37 270 bottom
FL20  120E  [EMIFIL_BLM15A_0402_0-6]  73.5 67 180 bottom
FL21  120E  [EMIFIL_BLM15A_0402_0-6]  80.92 73.9 180 bottom
FL22  120E  [EMIFIL_BLM15A_0402_0-6]  75.74 67.46 90 bottom
FL23  120E  [EMIFIL_BLM15A_0402_0-6]  114.48 62.79 0 top
J1  CON_AUDIOJACK6_STX-4235  [CON_AV6_STX-4235-3-3_S_R_T_26]  49.89 173.5 180 top
J2  CON_AUDIOJACK6_STX-4235  [CON_AV6_STX-4235-3-3_S_R_T_26]  67.03 173.5 180 top
J3  CON_AUDIOJACK6_STX-4235  [CON_AV6_STX-4235-3-3_S_R_T_26]  84.18 173.5 180 top
J4  CON_AUDIOJACK6_STX-4235  [CON_AV6_STX-4235-3-3_S_R_T_26]  101.58 173.5 180 top
J7  HDR_1X2  [HDR_1X2_90120-0122_S_T_5-6]  64.75 157.68 0 top
J9  HDR_1X3  [HDR_1X3_100_S_T]  31.61 160.86 90 top
J10  HDR_1X2  [HDR_1X2_90120-0122_S_T_5-6]  83.64 143.51 270 top
J12  RECP_40X2  [CON_40X2_QSE-040-01_S_S_S]  127.18 131.58 270 top
J13  RECP_40X2  [CON_40X2_QSE-040-01_S_S_S]  20.15 134.84 90 top
J14  HDR_2X10  [HDR_2X10_FTR-110-51-D-06_S_S_8-7]  41.36 108.57 180 top
J16  HDR_1X2  [HDR_1X2_61300211121_S_T_8-6]  23.64 41.14 90 top
J17  CON_MUSB-B_5_F  [CON_MUSBB5_629105150521_S_R_S_2-7]  12.7 50.01 270 top
J18  CON_BTOB_2X24_M  [CON_BTOB2X24_DF40GB-48DP_P_S_S_1-3]  87.81 40.98 0 top
J19  CON_BTOB_2X24_M  [CON_BTOB2X24_DF40GB-48DP_P_S_S_1-3]  120.24 40.98 0 top
J21  HDR_2X5  [HDR_2X5_PEC05DAAN_S_T_8-6]  31.21 30.4 90 top
J22  CON_MUSB-B_5_F  [CON_MUSBB5_629105150521_S_R_S_2-7]  66.15 2.7 0 top
J24  CON_USB-C_24_F  [CON_USBC24_2012670_S_R_S_3-9]  34.39 3.88 0 top
J25  CON_USB-C_24_F  [CON_USBC24_2012670_S_R_S_3-9]  49.39 3.88 0 top
J26  CON_SDCARD9_MEM2052-00-195-00-A  [CON_SD9_MEM2052-00-195-00_S_R_S_2]  129 74.57 270 bottom
J28  HDR_2X4  [HDR_2X4_90131-07_S_T_9-5]  104.74 124.66 0 top
J29  HDR_1X3  [HDR_1X3_87224-3_S_T_10-8]  114.88 120.27 90 top
J31  HDR_6X2  [HDR_6X2_100_S_T_5-5]  131.29 63.21 270 top
J32  HDR_1X2  [HDR_1X2_61300211121_S_T_8-6]  101.26 92.22 90 top
J33  HDR_1X2  [HDR_1X2_61300211121_S_T_8-6]  52.54 124.32 0 top
J34  HDR_1X2  [HDR_1X2_61300211121_S_T_8-6]  33.61 168.59 180 top
L2  2.2uH  [IND0806]  54.49 153.86 180 top
L3  2.2uH  [IND0806]  65.27 143.96 0 top
L4  0.22uH  [IND1210_1-2]  37.91 63.02 90 top
L5  0.22uH  [IND1210_1-2]  41.73 63.02 90 top
L6  0.22uH  [IND1210_1-2]  37.91 49.58 270 top
L7  0.22uH  [IND1210_1-2]  41.73 49.58 270 top
L10  90E  [IND4_DLW21H_90X60_SMD_1-4]  49.39 12.17 270 top
L11  0.47uH  [IND0806_1-2]  94.61 32.43 90 bottom
L24  6.8uH  [IND_XAL8080_330X350_SMD_8]  19.52 24.99 90 top
LD1  150080VS75000  [LED_150080VS75000_80X50_SMD_0-8]  75.14 132.2 90 top
LD2  150080VS75000  [LED_150080VS75000_80X50_SMD_0-8]  46.53 68.05 180 top
LD3  150040RS73220  [LED_150040GS73220_40X20_SMD_0-4]  47.03 79.41 90 top
LD4  150040VS73220  [LED_150040GS73220_40X20_SMD_0-4]  60.44 48.42 180 top
LD5  150080VS75000  [LED_150080VS75000_80X50_SMD_0-8]  41.97 77 0 top
LD6  150080VS75000  [LED_150080VS75000_80X50_SMD_0-8]  53.51 118.24 180 top
LD7  150080VS75000  [LED_150080VS75000_80X50_SMD_0-8]  52.46 31.75 90 top
LD9  150080VS75000  [LED_150080VS75000_80X50_SMD_0-8]  47.07 12.94 270 top
LD10  150080VS75000  [LED_150080VS75000_80X50_SMD_0-8]  72.11 128.76 270 top
LD13  150080VS75000  [LED_150080VS75000_80X50_SMD_0-8#2]  32.33 14.88 180 top
LD14  150040RS73220  [LED_150040GS73220_40X20_SMD_0-4]  35.43 38.03 90 top
NOREF  -  [unnamed]  20.16 161.83 180 top
NOREF#2  -  [unnamed]  133.17 3.9 270 top
NOREF#3  -  [unnamed]  3.94 4 270 top
NOREF#4  -  [unnamed]  100.74 3.9 270 top
NOREF#5  -  [unnamed]  4 172.94 0 top
NOREF#6  -  [unnamed]  13.69 8.75 0 top
NOREF#7  -  [unnamed#2]  9 92.45 270 top
NOREF#8  -  [unnamed#2]  9 140.37 270 top
NOREF#9  -  [#3]  10 177 0 top
NOREF#10  -  [#3]  -467.3 -5.8 0 top
NOREF#11  -  [#3]  -411.56 195.14 0 top
NOREF#12  -  [unnamed#2]  138 92.45 90 top
NOREF#13  -  [unnamed#2]  9 36.63 270 top
NOREF#14  -  [unnamed]  143 9.4 180 top
NOREF#15  -  [#3]  0 177 0 top
NOREF#16  -  [unnamed]  133.19 173.19 270 top
NOREF#17  -  [unnamed#2]  9 171.92 270 top
NOREF#18  -  [#3]  10 0 90 top
NOREF#19  -  [#3]  -47.87 -32.89 0 top
NOREF#20  -  [unnamed]  100.87 40.35 270 top
NOREF#21  -  [unnamed#2]  138 140.37 90 top
NOREF#22  -  [unnamed]  133.39 164.38 0 top
NOREF#23  -  [unnamed#2]  138 5.08 90 top
NOREF#24  -  [unnamed]  3.94 9.33 180 top
NOREF#25  -  [#3]  10.7 -33.17 0 top
NOREF#26  -  [unnamed]  4 167.6 0 top
NOREF#27  -  [unnamed]  76.74 40.35 270 top
NOREF#28  -  [unnamed]  143.06 173 90 top
NOREF#29  -  [unnamed]  143 4.06 180 top
NOREF#30  -  [unnamed]  13.69 164.38 0 top
NOREF#31  -  [unnamed]  13.81 173.19 90 top
NOREF#32  -  [unnamed]  127.17 158.58 180 top
NOREF#33  -  [unnamed]  143.06 167.67 0 top
NOREF#34  -  [unnamed#2]  138 36.63 90 top
NOREF#35  -  [unnamed]  133.3 40.35 270 top
NOREF#36  -  [unnamed]  20.16 107.84 0 top
NOREF#37  -  [unnamed]  127.17 104.59 0 top
NOREF#38  -  [unnamed#2]  138 171.92 90 top
NOREF#39  -  [#3]  -409.39 -163.3 0 top
NOREF#40  -  [unnamed]  109.17 40.35 270 top
NOREF#41  -  [unnamed#2]  9 5.08 270 top
NOREF#42  -  [unnamed]  13.81 3.81 90 top
NOREF#43  -  [unnamed]  133.39 164.38 180 bottom
NOREF#44  -  [unnamed]  13.69 164.38 180 bottom
NOREF#45  -  [unnamed]  3.94 9.33 180 bottom
NOREF#46  -  [unnamed]  4 167.6 180 bottom
NOREF#47  -  [unnamed]  143 9.4 0 bottom
NOREF#48  -  [unnamed]  143.06 167.67 0 bottom
Q1  CSD16301Q2  [WSON6_CSD13202Q2_80X80_0-8]  77.82 132.13 90 top
Q2  ABC817-40-HF  [SOT23-123_1-2]  49.77 70.41 90 bottom
Q3  BSS138LT1G  [SOT23-123_1-2]  63.36 48.42 180 top
Q4  BSS138LT1G  [SOT23-123_1-2]  24.96 59.04 0 top
Q5  CSD16301Q2  [WSON6_CSD13202Q2_80X80_0-8]  71.91 132.52 270 top
Q7  IRLML6401  [TO_SOT23-123]  28.56 107.7 90 top
Q8  CSD25310Q2  [SON6_CSD17313Q2_80X80]  55.37 17.12 0 bottom
Q9  CSD25310Q2  [SON6_CSD17313Q2_80X80]  52.67 17.12 180 bottom
Q10  CSD16301Q2  [WSON6_CSD13202Q2_80X80_0-8]  47.63 16.26 0 bottom
Q12  IRLML6401  [TO_SOT23-123]  67.02 117.96 270 top
R3  4.3K  [RES0402_0-5]  51.97 163.39 270 top
R4  4.3K  [RES0402_0-5]  53.24 163.39 270 top
R5  4.3K  [RES0402_0-5]  55.81 163.39 270 top
R6  4.3K  [RES0402_0-5]  57.08 163.39 270 top
R7  4.3K  [RES0402_0-5]  69.11 163.39 270 top
R8  4.3K  [RES0402_0-5]  70.38 163.39 270 top
R9  4.3K  [RES0402_0-5]  72.95 163.39 270 top
R10  4.3K  [RES0402_0-5]  74.22 163.39 270 top
R17  10K  [RES0201_0-5]  126.65 66.8 270 top
R18  10K  [RES0201_0-5]  129.09 68.35 270 top
R20  10K  [RES0201_0-5]  62.31 153.84 270 top
R21  0E  [RES0201_0-5]  128.16 69.62 180 top
R22  10K  [RES0201_0-5]  63.55 153.54 90 top
R23  10K  [RES0201_0-5]  64.44 153.54 270 top
R24  0E  [RES0201_0-5]  81.43 152.82 180 top
R25  0E  [RES0201_0-5]  98.82 152.82 180 top
R26  10K  [RES0201_0-5]  61.69 152.6 180 top
R27  10K  [RES0201_0-5]  107.64 150.88 180 top
R28  4.7K  [RES0201_0-5]  108.96 150.88 0 top
R29  10K  [RES0201_0-5]  88.81 150.53 180 top
R30  10K  [RES0201_0-5]  106.23 150.21 90 top
R31  10K  [RES0201_0-5]  87.5 149.99 0 top
R32  10K  [RES0201_0-5]  104.9 149.99 0 top
R33  10K  [RES0201_0-5]  90.82 149.93 0 top
R34  0E  [RES0201_0-5]  59.68 150.98 270 top
R35  22K  [RES0402_0-5]  107.59 149.66 0 top
R36  4.7K  [RES0201_0-5]  92.04 149.65 90 top
R37  0E  [RES0201_0-5]  88.53 149.36 90 top
R38  0E  [RES0402_0-5]  61.02 149.2 0 top
R46  0E  [RES0201_0-5]  58.63 148.01 180 top
R54  10K  [RES0201_0-5]  129.85 74.95 0 top
R55  10K  [RES0201_0-5]  125.35 75.45 180 top
R56  4.7K  [RES0201_0-5]  114.21 147.56 180 top
R57  10K  [RES0201_0-5]  129.85 75.89 0 top
R58  4.7K  [RES0201_0-5]  108.51 147.17 0 top
R60  10K  [RES0201_0-5]  55.32 144.27 90 top
R61  10K  [RES0201_0-5]  56.21 144.27 270 top
R62  10K  [RES0201_0-5]  57.1 144.27 90 top
R63  10K  [RES0201_0-5]  57.99 144.27 270 top
R64  10K  [RES0201_0-5]  125.36 76.4 180 top
R65  10K  [RES0201_0-5]  129.85 76.83 0 top
R66  10K  [RES0201_0-5]  125.35 77.33 180 top
R67  0E  [RES0603_0-75]  72.28 142.48 180 top
R68  10K  [RES0402_0-5]  76.5 142.38 270 top
R69  10K  [RES0402_0-5]  114.76 144.9 180 top
R70  10K  [RES0201_0-5]  121.54 78.41 90 top
R73  0E  [RES0201_0-5]  85.2 59.61 180 top
R74  0E  [RES0201_0-5]  85.21 58.64 180 top
R75  4.7K  [RES0201_0-5]  85.22 56.88 0 top
R76  4.7K  [RES0201_0-5]  85.22 57.64 180 top
R78  10K  [RES0402_0-5]  73.84 139.32 270 top
R81  33E  [RES0402_0-5]  38.47 162.61 270 top
R82  0E  [RES0402_0-5]  57.2 80.62 270 top
R83  4.7K  [RES0201_0-5]  87.26 62.18 270 top
R84  0E  [RES0201_0-5]  78.99 137.9 180 top
R85  4.7K  [RES0201_0-5]  88.21 62.18 90 top
R88  59E_1%  [RES0402_0-5]  34.16 157.29 90 top
R89  0E  [RES0201_0-5]  89.2 61.34 270 top
R90  10K  [RES0402_0-5]  77.14 136.21 180 top
R93  59E_1%  [RES0402_0-5]  34.16 159.32 90 top
R94  10K  [RES0201_0-5]  68.39 137.57 90 top
R97  0E  [RES0603_0-75]  93.94 59.41 0 top
R98  10K  [RES0201_0-5]  64.56 138.88 180 top
R102  0E  [RES0402_0-5]  37.54 155.46 0 top
R107  10K  [RES0201_0-5]  99.78 135.54 180 top
R108  0E  [RES0201_0-5]  105.61 136.2 270 top
R112  10K  [RES0201_0-5]  82.48 140.34 0 top
R115  100K  [RES0201_0-5]  109.94 96.9 0 top
R116  0E  [RES0201_0-5]  109.94 95.89 0 top
R117  10K  [RES0201_0-5]  115.16 94.27 270 top
R118  4.7K  [RES0201_0-5]  50.93 103.39 90 top
R119  4.7K  [RES0201_0-5]  52.2 103.39 90 top
R121  0E  [RES0201_0-5]  71.36 125.93 180 top
R122  10K  [RES0201_0-5]  70.15 126.21 90 top
R123  10K  [RES0201_0-5]  62.58 109.11 90 top
R124  10K  [RES0201_0-5]  65.25 128.12 90 top
R125  0E  [RES0201_0-5]  62.58 107.02 270 top
R126  1K  [RES0201_0-5]  87.05 128.22 90 top
R127  1K  [RES0201_0-5]  88.32 128.22 90 top
R128  1K  [RES0201_0-5]  89.59 128.22 90 top
R129  1K  [RES0201_0-5]  90.86 128.22 90 top
R130  1K  [RES0201_0-5]  92.13 128.22 90 top
R131  1K  [RES0201_0-5]  93.4 128.22 90 top
R132  1K  [RES0201_0-5]  94.67 128.22 90 top
R133  1K  [RES0201_0-5]  95.94 128.22 90 top
R134  1K  [RES0201_0-5]  74.54 128.22 90 top
R135  1K  [RES0201_0-5]  75.81 128.22 90 top
R136  1K  [RES0201_0-5]  77.08 128.22 90 top
R137  1K  [RES0201_0-5]  78.35 128.22 90 top
R138  1K  [RES0201_0-5]  79.62 128.22 90 top
R139  1K  [RES0201_0-5]  80.89 128.22 90 top
R140  1K  [RES0201_0-5]  82.16 128.22 90 top
R141  1K  [RES0201_0-5]  83.43 128.22 90 top
R143  10K  [RES0201_0-5]  100.35 60.53 180 top
R145  100K  [RES0201_0-5]  87.05 116.79 270 top
R146  100K  [RES0201_0-5]  88.32 116.79 270 top
R147  100K  [RES0201_0-5]  89.59 116.79 270 top
R148  100K  [RES0201_0-5]  90.86 116.79 270 top
R149  100K  [RES0201_0-5]  92.13 116.79 270 top
R150  100K  [RES0201_0-5]  93.4 116.79 270 top
R151  100K  [RES0201_0-5]  94.67 116.79 270 top
R152  100K  [RES0201_0-5]  95.94 116.79 270 top
R153  100K  [RES0201_0-5]  74.54 116.79 270 top
R154  100K  [RES0201_0-5]  75.81 116.79 270 top
R155  100K  [RES0201_0-5]  77.08 116.79 270 top
R156  100K  [RES0201_0-5]  78.35 116.79 270 top
R157  100K  [RES0201_0-5]  79.62 116.79 270 top
R158  100K  [RES0201_0-5]  80.89 116.79 270 top
R159  100K  [RES0201_0-5]  82.16 116.79 270 top
R160  100K  [RES0201_0-5]  83.43 116.79 270 top
R166  10K  [RES0201_0-5]  95.45 63.27 90 top
R170  0E  [RES0603_0-75]  80.08 72.67 90 top
R176  0E  [RES0402_0-5]  82.43 100.29 90 bottom
R177  0E  [RES0402_0-5]  81.83 98.28 90 bottom
R178  22E  [RES0402_0-5]  76.58 97.45 270 top
R179  22E  [RES0402_0-5]  79.07 97.45 270 top
R180  220E  [RES0402_0-5]  75.06 134.78 180 top
R190  0E  [RES0402_0-5]  71.16 97.19 90 bottom
R191  0E  [RES0402_0-5]  79.94 100.29 90 bottom
R195  470E  [RES0402_0-5]  34.22 38.04 90 top
R197  0E  [RES0402_0-5]  65.96 95.57 270 top
R202  10K  [RES0201_0-5]  128.75 74.07 180 top
R203  10K  [RES0201_0-5]  79.68 131.44 270 top
R205  0E  [RES0201_0-5]  84.41 76.07 0 bottom
R206  0E  [RES0402_0-5]  64.62 95.54 270 top
R210  62E_1%  [RES0402_0-5]  76.7 65.86 270 top
R211  10K  [RES0201_0-5]  27.59 103.48 0 top
R212  10K  [RES0201_0-5]  27.59 104.24 0 top
R213  0E  [RES0402_0-5]  77.98 130.05 0 top
R214  1K  [RES0201_0-5]  46.3 100.18 90 top
R216  22E  [RES0201_0-5]  77.75 69.24 90 top
R217  1K  [RES0201_0-5]  46.31 102.01 270 top
R218  4.87K_1%  [RES0402_0-5]  33.79 100.26 90 top
R219  0E  [RES0201_0-5]  13.05 83.08 90 top
R220  10K  [RES0201_0-5]  31.64 104.47 180 top
R221  0E  [RES0201_0-5]  13.45 92.58 270 top
R224  0E  [RES0201_0-5]  13.94 83.08 90 top
R225  10K  [RES0201_0-5]  32.03 103.49 270 top
R227  0E  [RES0201_0-5]  14.34 92.58 270 top
R228  0E  [RES0201_0-5]  85.6 89.25 0 top
R229  1K_1%  [RES0402_0-5]  29.92 98.17 270 top
R230  1K_1%  [RES0402_0-5]  31.19 98.17 270 top
R231  1K_1%  [RES0402_0-5]  32.46 98.17 270 top
R232  1K_1%  [RES0402_0-5]  33.73 98.17 270 top
R233  0E  [RES0201_0-5]  14.83 83.08 90 top
R234  62E_1%  [RES0402_0-5]  86.03 77.75 0 bottom
R235  0E  [RES0201_0-5]  15.23 92.58 270 top
R236  4.7K  [RES0201_0-5]  39.53 97.29 270 top
R237  4.7K  [RES0201_0-5]  40.3 97.29 270 top
R238  4.7K  [RES0201_0-5]  97.01 93.14 90 top
R239  0E  [RES0201_0-5]  85.21 86.46 270 top
R240  10K  [RES0201_0-5]  48.82 83.56 270 top
R241  4.7K  [RES0201_0-5]  46.48 95.74 90 top
R242  10K  [RES0201_0-5]  95.6 91.78 0 top
R243  0E  [RES0402_0-5]  45.72 56.95 0 bottom
R246  49.9E_1%  [RES0402_0-5]  26.29 93.64 180 top
R249  0E  [RES0201_0-5]  62.98 76.49 270 top
R252  0E  [RES0201_0-5]  62.7 76.21 0 top
R253  0E  [RES0201_0-5]  62.71 75.13 0 top
R254  0E  [RES0201_0-5]  62.99 74.85 90 top
R255  100K_1%  [RES0402_0-5]  50.32 77.5 180 top
R256  62E_1%  [RES0402_0-5]  54.63 84.87 0 top
R258  182K_1%  [RES0402_0-5]  48.82 77.01 270 top
R259  4.7K  [RES0201_0-5]  54.14 83.62 90 top
R260  220E  [RES0402_0-5]  47.11 70.46 90 bottom
R261  0E  [RES0201_0-5]  61.07 75.99 270 bottom
R262  10K  [RES0201_0-5]  99.51 76.15 0 top
R263  10K  [RES0201_0-5]  99.3 75.37 0 top
R264  10K  [RES0201_0-5]  99.3 74.22 0 top
R265  0.001E_1%  [RES_CST0612_0612-4_0-9]  37.38 68.33 270 top
R266  10K  [RES0201_0-5]  99.3 73.08 0 top
R267  10K  [RES0201_0-5]  99.3 71.94 0 top
R268  10K  [RES0201_0-5]  53.36 75.11 90 top
R269  10K  [RES0201_0-5]  99.3 70.79 0 top
R270  10K  [RES0201_0-5]  99.3 69.65 0 top
R271  0E  [RES0201_0-5]  27.65 82.3 180 top
R272  1K  [RES0402_0-5]  51.74 71.78 180 bottom
R275  10K  [RES0201_0-5]  99.3 68.51 0 top
R276  220E  [RES0402_0-5]  47.03 81.52 270 top
R277  1K  [RES0402_0-5]  21.06 80.97 180 top
R278  10K  [RES0201_0-5]  22.77 80.96 180 top
R280  10K  [RES0201_0-5]  21.36 78.88 0 top
R281  0E  [RES0201_0-5]  47.89 62.52 270 top
R282  10K  [RES0201_0-5]  48.68 62.52 270 top
R283  0E  [RES0201_0-5]  24.9 79.17 180 top
R284  62E_1%  [RES0402_0-5]  62.19 88.23 270 top
R285  10K  [RES0201_0-5]  24.9 78.23 0 top
R286  0E  [RES0201_0-5]  65.78 47.19 90 top
R287  220E  [RES0402_0-5]  44.36 78.01 270 top
R288  10K  [RES0201_0-5]  50.03 61.12 0 top
R289  20K_1%  [RES0402_0-5]  46.04 77.63 0 top
R290  0E  [RES0201_0-5]  48.04 60.83 270 top
R291  10K  [RES0201_0-5]  48.83 60.83 270 top
R292  220E  [RES0402_0-5]  60.43 49.43 0 top
R293  0E  [RES0201_0-5]  23.81 61.57 270 top
R294  0E  [RES0201_0-5]  32.02 57.91 0 top
R295  30K  [RES0402_0-5]  45.06 76.43 0 top
R296  0E  [RES0201_0-5]  35.51 58.61 0 top
R297  0E  [RES0201_0-5]  34.26 59.67 0 top
R298  2K_1%  [RES0402_0-5]  27.62 58.55 90 top
R299  0E  [RES0201_0-5]  48.67 59.33 90 top
R300  0E  [RES0201_0-5]  49.46 59.33 90 top
R301  4.7K  [RES0201_0-5]  60.64 88.72 0 top
